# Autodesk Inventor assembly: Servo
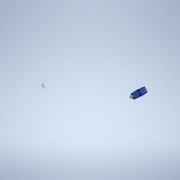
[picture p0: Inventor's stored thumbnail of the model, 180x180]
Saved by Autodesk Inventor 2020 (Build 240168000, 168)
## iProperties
Created: 2002-01
Part Number: Servo
Document SubType Name: Assemblage
Designer: Philippe
Mass: 2.28348 g
Surface Area: 60.8084 cm^2
Volume: 2.28348 cm^3
Density: 1 g/cm^3
Control State: 0
Master: False
Checked Out: False
Shininess: 41.0
Angle Display Precision: 2
Document Length Units: 11269
Document Angle Units: 11279
Document Time Units: 11290
Document Mass Units: 11283
Document Length Units Precision: 3
Document Angle Units Precision: 2
Density: 0.0
Volumn: 0.0
Area: 0.0
PropertySet Name: Model Information
Author: Philippe
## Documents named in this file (13)
- C:\Users\bruno\OneDrive\Bureau\Robot-Inventor\Robot-equilibrage\Servo\Servo.iam
- C:\Users\bruno\OneDrive\Bureau\Robot-Inventor\Robot-equilibrage\Servo\Couvercle inférieur.ipt
- C:\Users\bruno\OneDrive\Bureau\Robot-Inventor\Robot-equilibrage\Servo\Boitier.ipt
- C:\Users\bruno\OneDrive\Bureau\Robot-Inventor\Robot-equilibrage\Servo\Couvercle supérieur.ipt
- C:\Users\bruno\OneDrive\Bureau\Robot-Inventor\Robot-equilibrage\Servo\Moteur.ipt
- C:\Users\bruno\OneDrive\Bureau\Robot-Inventor\Robot-equilibrage\Servo\Pignon moteur.ipt
- C:\Users\bruno\OneDrive\Bureau\Robot-Inventor\Robot-equilibrage\Servo\Axe central.ipt
- C:\Users\bruno\OneDrive\Bureau\Robot-Inventor\Robot-equilibrage\Servo\Mobile 2-3.ipt
- C:\Users\bruno\OneDrive\Bureau\Robot-Inventor\Robot-equilibrage\Servo\Mobile 4-5.ipt
- C:\Users\bruno\OneDrive\Bureau\Robot-Inventor\Robot-equilibrage\Servo\Potentiomètre.ipt
- C:\Users\bruno\OneDrive\Bureau\Robot-Inventor\Robot-equilibrage\Servo\Mobile 6-7.ipt
- C:\Users\bruno\OneDrive\Bureau\Robot-Inventor\Robot-equilibrage\Servo\Roue 8.ipt
- C:\Users\bruno\OneDrive\Bureau\Robot-Inventor\Robot-equilibrage\Servo\ISO 7049 - ST 2.2 x 4.5 - F - H.ipt
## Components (12 placed, 12 different names)
1. Boitier:1 — Plaquage1, Plaquage2, Placage:1, Placage:2, Logement:1, Angle:1, Placage:3, Placage:4, Placage:6, Orientation, Placage:7, Logement:3, Logement:4
2. Couvercle inférieur:1 — Plaquage1, Placage:3, Placage:4
3. Couvercle supérieur:1 — Plaquage2, Placage:1, Placage:2, Angle:5
4. Moteur:1 — Logement:1, Angle:1, Logement:2
5. Pignon moteur:1 — Logement:2, Rotation:1
6. Axe central:1 — Angle:2, Placage:5, Logement:3, Angle:3, Placage:9
7. Mobile 2-3:1 — Angle:2, Placage:5, Placage:6, Rotation:1, Placage:8, Rotation:2, Placage:10
8. Mobile 4-5:1 — Orientation, Placage:7, Placage:8, Rotation:2, Rotation:3, Placage:11
9. Potentiomètre:1 — Logement:4, Placage:12
10. Mobile 6-7:1 — Angle:3, Placage:9, Placage:10, Rotation:3, Rotation:4
11. Roue 8:1 — Placage:11, Placage:12, Rotation:4, Angle:5
12. ISO 7049 - ST 2.2 x 4.5 - F - H:1
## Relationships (27: Mate 14, Angle 5, Insert 4, RelateRotation 4)
- Plaquage1 [Mate]: Boitier:1 ↔ Couvercle inférieur:1
- Plaquage2 [Mate]: Boitier:1 ↔ Couvercle supérieur:1
- Placage:1 [Mate]: Boitier:1 ↔ Couvercle supérieur:1
- Placage:2 [Mate]: Boitier:1 ↔ Couvercle supérieur:1
- Logement:1 [Insert]: Boitier:1 ↔ Moteur:1
- Angle:1: Boitier:1 ↔ Moteur:1
- Placage:3 [Mate]: Boitier:1 ↔ Couvercle inférieur:1
- Placage:4 [Mate]: Boitier:1 ↔ Couvercle inférieur:1
- Logement:2 [Insert]: Moteur:1 ↔ Pignon moteur:1
- Angle:2: Axe central:1 ↔ Mobile 2-3:1
- Placage:5 [Mate]: Axe central:1 ↔ Mobile 2-3:1
- Placage:6 [Mate]: Boitier:1 ↔ Mobile 2-3:1
- Rotation:1 [RelateRotation]: Pignon moteur:1 ↔ Mobile 2-3:1
- Orientation [Angle]: Boitier:1 ↔ Mobile 4-5:1
- Placage:7 [Mate]: Boitier:1 ↔ Mobile 4-5:1
- Placage:8 [Mate]: Mobile 2-3:1 ↔ Mobile 4-5:1
- Logement:3 [Insert]: Boitier:1 ↔ Axe central:1
- Rotation:2 [RelateRotation]: Mobile 2-3:1 ↔ Mobile 4-5:1
- Logement:4 [Insert]: Boitier:1 ↔ Potentiomètre:1
- Angle:3: Axe central:1 ↔ Mobile 6-7:1
- Placage:9 [Mate]: Axe central:1 ↔ Mobile 6-7:1
- Placage:10 [Mate]: Mobile 2-3:1 ↔ Mobile 6-7:1
- Rotation:3 [RelateRotation]: Mobile 4-5:1 ↔ Mobile 6-7:1
- Placage:11 [Mate]: Mobile 4-5:1 ↔ Roue 8:1
- Placage:12 [Mate]: Potentiomètre:1 ↔ Roue 8:1
- Rotation:4 [RelateRotation]: Mobile 6-7:1 ↔ Roue 8:1
- Angle:5: Couvercle supérieur:1 ↔ Roue 8:1
